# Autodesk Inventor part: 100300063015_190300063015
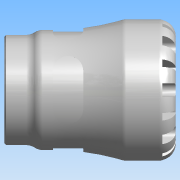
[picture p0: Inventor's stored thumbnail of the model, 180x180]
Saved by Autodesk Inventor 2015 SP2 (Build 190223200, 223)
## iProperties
Created: 2016-12
Part Number: 100300063015_190300063015
Material: PVC-Piping
Description: PLASSON FEMALE ADAPTOR 63X1.1/2" SERIES 1
Document SubType Name: Modeling
Designer: KIM
Mass: 664.223 g
Surface Area: 733.008 cm^2
Volume: 474.445 cm^3
Density: 1.4 g/cm^3
Appearance: Smooth - White
Author: KIM
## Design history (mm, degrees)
derived "1003.ipt"
feature "Solid1::1003.ipt"
tag "TaggingFeature1"
body "Solid1"
other parameters: "d0" = 125, "d1" = 37.8, "d2" = 63, "d3" = 78.75, "d4" = 103, "d8" = 87.55, "d13" = 9.7, "d14" = 9.7, "d15" = 0, "d17" = 360 deg, "d19" = 8 deg, "d20" = 1.26, "d21" = 1.26, "d22" = 8 deg, "d24" = 0, "d26" = 360 deg, "d32" = 10.3, "d33" = 10.3, "d39" = 1.34535, "d42" = 44.845, "d43" = 80.34, "d46" = 5.25, "d47" = 24, "d48" = 42.60275, "d50" = 3.63, "d51" = 1.03, "d54" = 22.05, "d55" = 13.86, "d57" = 19.012, "d58" = 0, "d68" = 360 deg, "d72" = 1.26, "d74" = 0, "d76" = 18.7425, "d_" = 63, "E_" = 103, "H_" = 125, "Rp" = 44.845, "l_2" = 24, "d9" = 12.125, "d11" = 103, "d12" = 78.75, "d49" = 11
